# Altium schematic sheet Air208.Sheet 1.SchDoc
size 431 x 279 mm
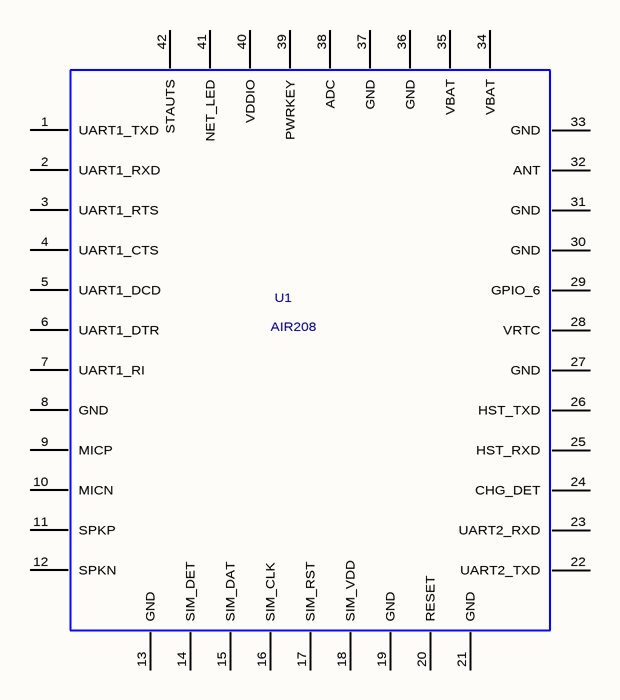
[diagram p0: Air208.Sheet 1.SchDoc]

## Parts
U1  AIR208  [AIR208]

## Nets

Not connected (* = marked no-connect by the designer): U1 1(UART1_TXD) 2(UART1_RXD) 3(UART1_RTS) 4(UART1_CTS) 5(UART1_DCD) 6(UART1_DTR) 7(UART1_RI) 8(GND) 9(MICP) 10(MICN) 11(SPKP) 12(SPKN) 13(GND) 14(SIM_DET) 15(SIM_DAT) 16(SIM_CLK) 17(SIM_RST) 18(SIM_VDD) 19(GND) 20(RESET) 21(GND) 22(UART2_TXD) 23(UART2_RXD) 24(CHG_DET) 25(HST_RXD) 26(HST_TXD) 27(GND) 28(VRTC) 29(GPIO_6) 30(GND) 31(GND) 32(ANT) 33(GND) 34(VBAT) 35(VBAT) 36(GND) 37(GND) 38(ADC) 39(PWRKEY) 40(VDDIO) 41(NET_LED) 42(STAUTS)

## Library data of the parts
U1 = AIR208: Geometry.Height: 2.3 mm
